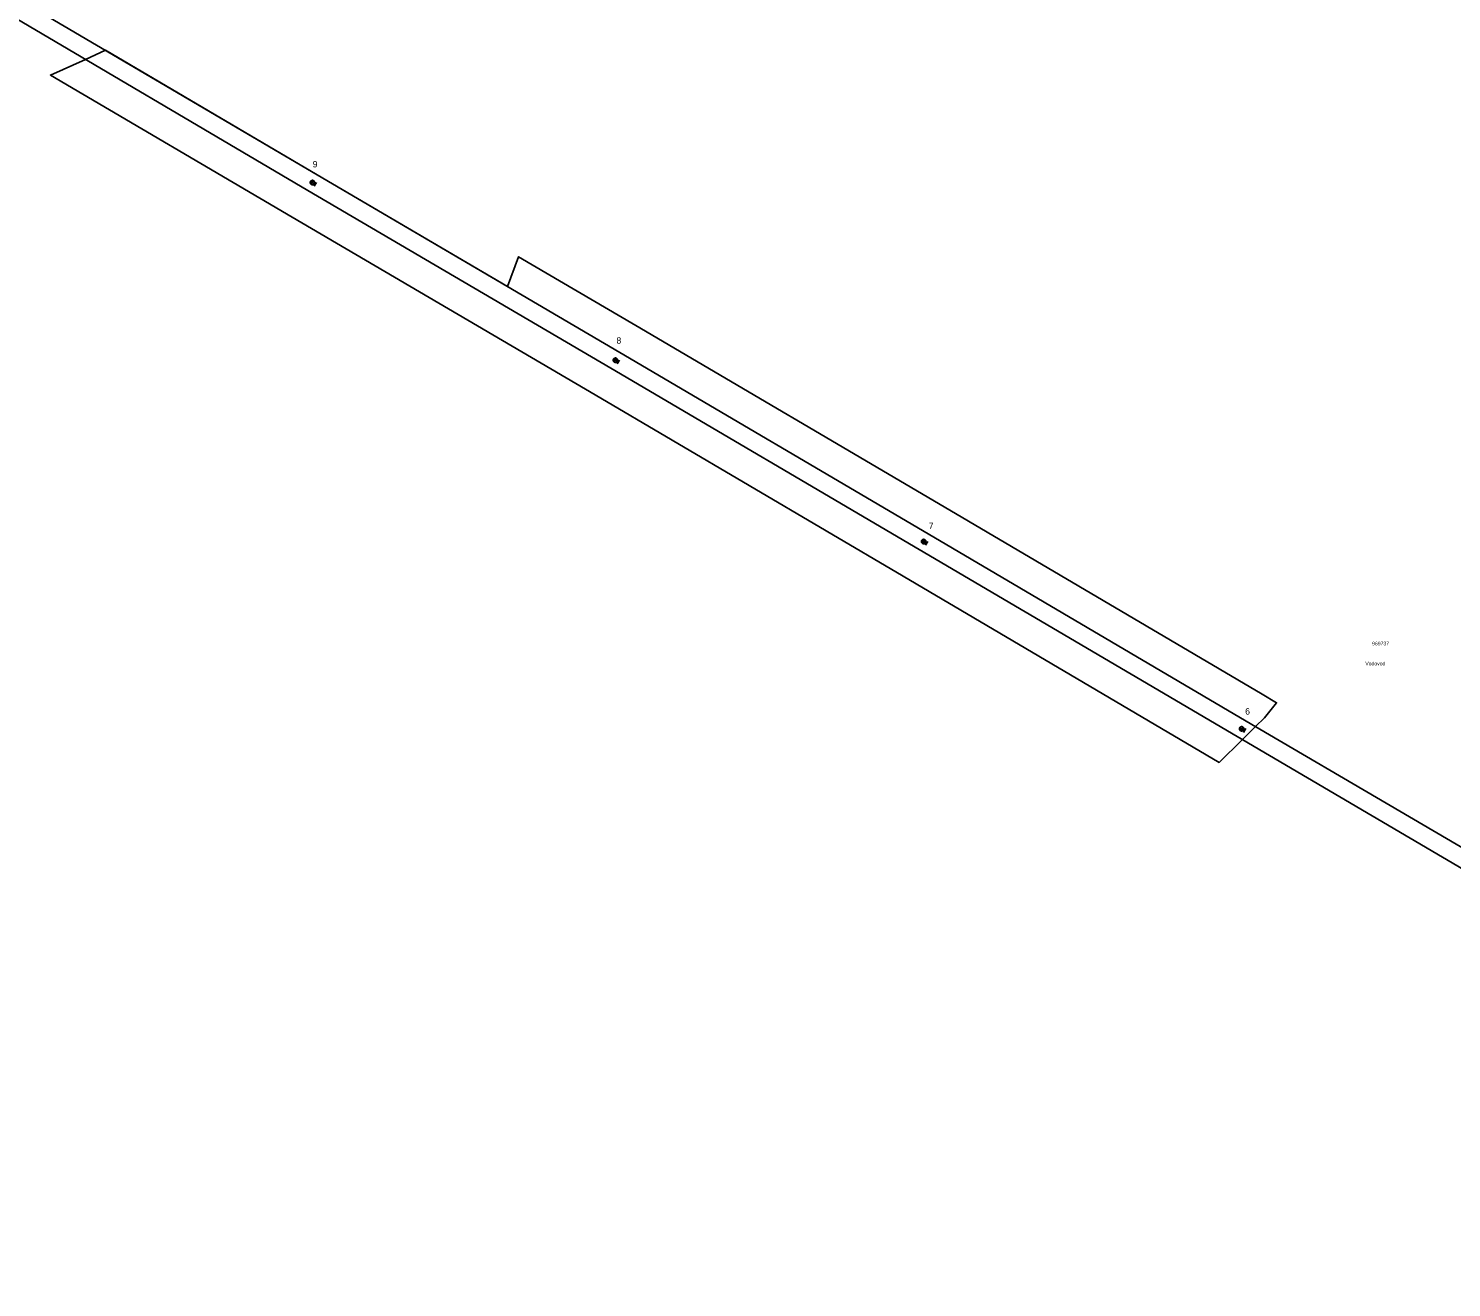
# Model space of a CAD drawing. Extents: x -788491 to -785797, y -1154753 to -1152002.
# Drawn here: x -788279.1 to -787892.1, y -1153659.3 to -1153317 of the extents above; entities that cross this region are included whole.
import ezdxf

# ---------------------------------------------------------------- set-up
doc = ezdxf.new("R2010")
doc.units = 0
for name, color, linetype in [('Vrstva 1', 7, 'Continuous'), ('Vrstva 13', 7, 'Continuous'), ('Vrstva 14', 7, 'Continuous'), ('Vrstva 2', 7, 'Continuous'), ('Vrstva 26', 7, 'Continuous'), ('Vrstva 27', 7, 'Continuous'), ('Vrstva 35', 7, 'Continuous')]:
    doc.layers.add(name, color=color, linetype=linetype)

# ---------------------------------------------------------------- blocks, each defined once
blk = doc.blocks.new('VN410')
at = {"layer": 'Vrstva 2'}
for points in [[(0, 1.24), (-0.13, 1.23), (-0.25, 1.21), (-0.38, 1.18), (-0.5, 1.13), (-0.61, 1.07), (-0.72, 1), (-0.82, 0.92), (-0.91, 0.83), (-0.99, 0.73), (-1.06, 0.62), (-1.12, 0.51), (-1.17, 0.39), (-1.2, 0.26), (-1.22, 0.14), (-1.23, 0.01), (-1.22, -0.12), (-1.2, -0.25), (-1.17, -0.37), (-1.12, -0.49), (-1.06, -0.61), (-0.99, -0.71), (-0.91, -0.81), (-0.82, -0.91), (-0.72, -0.99), (-0.61, -1.06), (-0.5, -1.11), (-0.38, -1.16), (-0.25, -1.19), (-0.13, -1.21), (0, -1.22), (0.13, -1.21), (0.26, -1.19), (0.38, -1.16), (0.5, -1.11), (0.61, -1.06), (0.72, -0.99), (0.82, -0.91), (0.91, -0.81), (0.99, -0.71), (1.06, -0.61), (1.12, -0.49), (1.17, -0.37), (1.2, -0.25), (1.22, -0.12), (1.23, 0.01), (1.22, 0.14), (1.2, 0.26), (1.17, 0.39), (1.12, 0.51), (1.06, 0.62), (0.99, 0.73), (0.91, 0.83), (0.82, 0.92), (0.72, 1), (0.61, 1.07), (0.5, 1.13), (0.38, 1.18), (0.26, 1.21), (0.13, 1.23), (0, 1.24)], [(-1.23, 0), (1.23, 0)], [(0, -1.23), (0, 1.23)], [(1.86, -1.23), (1.86, 1.23)]]:
    blk.add_lwpolyline(points, dxfattribs=at)

msp = doc.modelspace()

# ---------------------------------------------------------------- linework, layer by layer
at = {"layer": 'Vrstva 1'}
for points in [[(-787693.49, -1153655.09), (-787779.49, -1153604.55), (-787864.38, -1153554.21), (-787947.97, -1153505.29), (-788034.41, -1153454.37), (-788118.23, -1153405.06), (-788200.61, -1153356.75), (-788287.07, -1153305.87), (-788373.48, -1153255.21), (-788458.44, -1153205.03)], [(-787695.97, -1153659.31), (-787781.98, -1153608.77), (-787866.65, -1153558.66), (-787950.45, -1153509.51), (-788036.89, -1153458.59), (-788120.71, -1153409.28), (-788203.09, -1153360.97), (-788289.55, -1153310.09), (-788375.96, -1153259.43), (-788461.16, -1153209.11)]]:
    msp.add_lwpolyline(points, dxfattribs=at)
at = {"layer": 'Vrstva 35'}
msp.add_lwpolyline([(-788200.61, -1153356.75), (-788148.83, -1153387.12), (-788145.8, -1153379.03), (-788113.92, -1153397.73), (-788030.1, -1153447.04), (-787943.66, -1153497.96), (-787939.69, -1153500.28), (-787942.98, -1153504.36), (-787945.43, -1153506.78), (-787949.05, -1153510.34), (-787955.31, -1153516.51), (-788041.21, -1153465.92), (-788125.02, -1153416.61), (-788207.4, -1153368.3), (-788273.09, -1153329.64), (-788263.6, -1153325.37), (-788258.13, -1153322.9)], close=True, dxfattribs=at)

# ---------------------------------------------------------------- block references
at = {"layer": 'Vrstva 13'}
for p, xscale, yscale, rotation in [((-788201.85, -1153358.86), 0.49999999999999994, 0.5000000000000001, -30.564880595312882), ((-788119.47, -1153407.17), 0.5000000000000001, 0.4999999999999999, -30.672641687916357), ((-788035.65, -1153456.48), 0.5, 0.5, -30.82995840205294), ((-787949.21, -1153507.4), 0.5, 0.5, -30.576408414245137)]:
    msp.add_blockref('VN410', p, dxfattribs=dict(at, xscale=xscale, yscale=yscale, rotation=rotation))

# ---------------------------------------------------------------- texts
at = {"layer": 'Vrstva 14'}
for s, p in [('9', (-788201.78, -1153354.74)), ('8', (-788119.19, -1153402.66)), ('7', (-788034.27, -1153453.06)), ('6', (-787948.24, -1153503.51))]:
    msp.add_text(s, height=1.75, dxfattribs=at).set_placement(p)
at = {"layer": 'Vrstva 26'}
msp.add_text('969737', height=1, dxfattribs=at).set_placement((-787913.72, -1153484.7))
at = {"layer": 'Vrstva 27'}
msp.add_text('Vodovod', height=1, dxfattribs=at).set_placement((-787915.57, -1153490.15))

doc.saveas('drawing.dxf')
